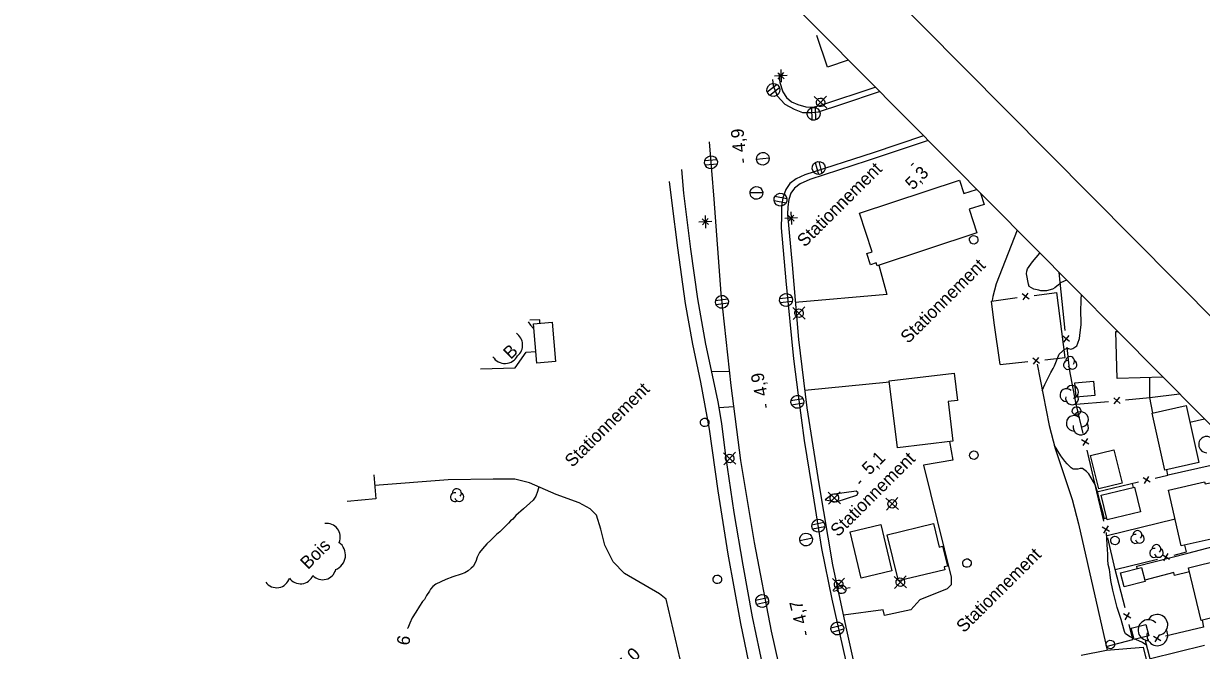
# Model space of a CAD drawing. Extents: x 381879 to 384696, y 5564785 to 5567594.
# Drawn here: x 383466.9 to 383743.2, y 5566826.8 to 5566973.9 of the extents above; entities that cross this region are included whole.
import ezdxf

# ---------------------------------------------------------------- set-up
doc = ezdxf.new("R2010")
doc.units = 0
for name, color, linetype in [('Niveau 19', 7, 'Continuous'), ('Niveau 2', 7, 'Continuous'), ('Niveau 21', 7, 'Continuous'), ('Niveau 22', 7, 'Continuous'), ('Niveau 3', 7, 'Continuous'), ('Niveau 31', 7, 'Continuous'), ('Niveau 36', 7, 'Continuous'), ('Niveau 37', 7, 'Continuous'), ('Niveau 44', 7, 'Continuous'), ('Niveau 52', 7, 'Continuous'), ('Niveau 60', 7, 'Continuous')]:
    doc.layers.add(name, color=color, linetype=linetype)

msp = doc.modelspace()

# ---------------------------------------------------------------- linework, layer by layer
at = {"layer": 'Niveau 19'}
for points in [[(383628.27, 5566892.24), (383632.51, 5566892.37)], [(383731.04, 5566886.19), (383731.06, 5566890.82)], [(383731.76, 5566882.51), (383731.04, 5566886.19), (383738.02, 5566887.03)], [(383633.53, 5566884.02), (383629.98, 5566883.76)], [(383743.88, 5566881.12), (383740.46, 5566880.28)], [(383735.4, 5566868.06), (383745.46, 5566870.32), (383750.86, 5566871.42)], [(383727.22, 5566865.09), (383727.01, 5566865.98)], [(383720.14, 5566857.72), (383720.96, 5566857.92)], [(383736.97, 5566857.62), (383721.08, 5566853.75)], [(383728.12, 5566846.05), (383728, 5566846.61), (383740.01, 5566849.62), (383750.71, 5566852.49), (383755.18, 5566853.7)], [(383740.33, 5566845.31), (383736.85, 5566844.41), (383736.66, 5566845.12), (383729.89, 5566843.36)], [(383743.88, 5566827.96), (383731.25, 5566824.83)]]:
    msp.add_lwpolyline(points, dxfattribs=at)
at = {"layer": 'Niveau 2'}
for points in [[(383711.54, 5566913.72), (383710.14, 5566913.05), (383709.67, 5566912.63), (383708.79, 5566911.9), (383708.21, 5566911.6), (383706.83, 5566911.17), (383705.5, 5566911.18), (383705, 5566911.36), (383703.85, 5566911.57), (383702.79, 5566912.2), (383702.63, 5566912.78), (383702.14, 5566915.17), (383702.2, 5566915.79), (383702.4, 5566916.36), (383702.73, 5566916.9), (383703.57, 5566918), (383705.3, 5566920.01)], [(383705.82, 5566887.83), (383706.45, 5566889.24), (383707.25, 5566890.76), (383707.85, 5566892.06), (383708.43, 5566892.98), (383708.72, 5566893.6), (383709.37, 5566895.2), (383709.79, 5566896.35), (383710.56, 5566897.03), (383711, 5566897.46), (383711.49, 5566897.63), (383712, 5566897.67), (383712.51, 5566897.53), (383713.03, 5566897.63), (383713.92, 5566898.3), (383714.16, 5566898.95), (383714.58, 5566900.01), (383714.68, 5566900.72), (383714.98, 5566903.31), (383714.95, 5566904.6), (383714.85, 5566905.67), (383714.86, 5566907.15), (383714.99, 5566908.22), (383714.99, 5566909.32), (383715.03, 5566910.2)], [(383585.28, 5566903.94), (383585.83, 5566903.16), (383586.62, 5566902.26)], [(383720.45, 5566857.79), (383720.22, 5566858.73), (383719.59, 5566861), (383718.92, 5566863.49), (383718.23, 5566865.77), (383717.87, 5566866.4), (383716.73, 5566868.27), (383716.23, 5566868.82), (383715.25, 5566869.55), (383714.73, 5566869.55), (383714.16, 5566869.38), (383713.12, 5566869.39), (383712.65, 5566869.66), (383711.64, 5566870.59), (383711.14, 5566871.2), (383710.17, 5566872.49), (383708.68, 5566874.89)], [(383587.78, 5566865.2), (383587.48, 5566864.09), (383587.08, 5566863.01), (383586.46, 5566862.08), (383585.68, 5566861.35), (383584.15, 5566860.05), (383582.41, 5566858.51), (383581.65, 5566857.64), (383581.11, 5566857.23), (383580.65, 5566856.71), (383578.64, 5566854.64), (383577.87, 5566854.02), (383576.55, 5566852.7), (383575.57, 5566851.81), (383574.56, 5566850.69), (383573.86, 5566849.82), (383573.32, 5566848.75), (383573.02, 5566847.71), (383572.36, 5566846.54), (383571.88, 5566846.17), (383571.2, 5566845.48), (383570.45, 5566845.02), (383569.55, 5566844.75), (383567.57, 5566844.1), (383565.95, 5566843.5), (383563.59, 5566842.41), (383562.95, 5566841.87), (383562.38, 5566841.24), (383562.11, 5566840.77), (383561.39, 5566839.73), (383560.92, 5566838.78), (383560.49, 5566838.31), (383559.76, 5566837.24), (383558.89, 5566835.85), (383558.08, 5566834.46), (383557.51, 5566833.27), (383557.03, 5566832.04), (383557.01, 5566831.98)], [(383724.35, 5566834.11), (383723.41, 5566836.93), (383723.01, 5566838.44), (383722.36, 5566841), (383721.93, 5566843.24), (383721.8, 5566844.57), (383721.57, 5566845.8), (383721.28, 5566846.98), (383721.18, 5566848.18), (383721.23, 5566849.41), (383721.13, 5566850.52), (383721.01, 5566852.91), (383720.91, 5566854.49)], [(383727.3, 5566829.63), (383726.42, 5566830.01), (383725.38, 5566830.73), (383725.12, 5566831.26), (383724.97, 5566831.82), (383724.35, 5566834.11)], [(383730.33, 5566827.97), (383729.31, 5566828.67), (383727.81, 5566829.41), (383727.64, 5566829.48)]]:
    msp.add_lwpolyline(points, dxfattribs=at)
at = {"layer": 'Niveau 21'}
for p, q in [((383643.8, 5566962.31), (383645.28, 5566960.95)), ((383643.88, 5566960.87), (383645.22, 5566962.37)), ((383644.49, 5566963.12), (383644.61, 5566960.12)), ((383646.05, 5566961.68), (383643.05, 5566961.56)), ((383626.75, 5566928.89), (383626.87, 5566925.89)), ((383646.18, 5566928.92), (383647.66, 5566927.56)), ((383646.26, 5566927.48), (383647.6, 5566928.98)), ((383646.87, 5566929.73), (383646.99, 5566926.73)), ((383628.31, 5566927.45), (383625.31, 5566927.33)), ((383626.06, 5566928.08), (383627.54, 5566926.72)), ((383626.14, 5566926.64), (383627.48, 5566928.14)), ((383648.43, 5566928.29), (383645.43, 5566928.17))]:
    msp.add_line(p, q, dxfattribs=at)
for points in [[(383642.56, 5566960.77), (383642.74, 5566959.36), (383643.67, 5566956.91), (383645.45, 5566954.99), (383647.62, 5566953.77), (383649.64, 5566953.02), (383651.76, 5566952.99), (383653.39, 5566953.22), (383658.82, 5566954.99), (383667.67, 5566957.94)], [(383737.49, 5566590.78), (383727.69, 5566609.79), (383718.09, 5566629.17), (383707.78, 5566649.57), (383698.39, 5566667.64), (383691.2, 5566682.96), (383683.79, 5566699.61), (383679.21, 5566710.93), (383672.16, 5566728.73), (383667.29, 5566742.33), (383662.12, 5566758.01), (383656.42, 5566775.1), (383651.76, 5566791.49), (383647.32, 5566809.08), (383642.31, 5566831.38), (383638.34, 5566852.16), (383635.18, 5566871.36), (383632.88, 5566888.99), (383630.5, 5566910.54), (383628.88, 5566932.68), (383627.83, 5566946.15)], [(383678, 5566947.53), (383666.2, 5566943.55), (383650.16, 5566938.44), (383648.13, 5566937.44), (383646.62, 5566936.34), (383645.69, 5566934.95), (383644.98, 5566933.04), (383644.71, 5566931.02), (383644.66, 5566928.83), (383644.62, 5566925.96), (383645.71, 5566913.54), (383647.49, 5566895.24), (383648.58, 5566886.69), (383650.03, 5566876.11), (383651.78, 5566865.06), (383654.07, 5566850.75), (383656.51, 5566838.83), (383659.71, 5566824.66)]]:
    msp.add_lwpolyline(points, dxfattribs=at)
at = {"layer": 'Niveau 22'}
for points in [[(383644.06, 5566962.25), (383644.29, 5566960.05), (383645.03, 5566957.84), (383645.83, 5566956.53), (383647.05, 5566955.55), (383648.51, 5566954.9), (383650.39, 5566954.37), (383652.01, 5566954.25), (383653.92, 5566954.72), (383666.64, 5566958.98)], [(383679.09, 5566946.43), (383664.74, 5566941.69), (383651.33, 5566937.32), (383649.04, 5566936.29), (383647.77, 5566935.31), (383646.9, 5566934.08), (383646.42, 5566932.62), (383646.2, 5566930.91), (383646.12, 5566929.13), (383647.18, 5566917.26), (383648.66, 5566899.78), (383650.66, 5566883.73), (383653.41, 5566865.9), (383656.68, 5566846.9), (383659.8, 5566832.31), (383662.88, 5566818.25)], [(383621.26, 5566939.64), (383621.73, 5566934.14), (383623.33, 5566920.99), (383624.95, 5566909.35), (383626.87, 5566898.7), (383628.68, 5566890.35), (383629.73, 5566885.18), (383630.63, 5566880.04), (383631.54, 5566872.5), (383633.51, 5566859.18), (383635.58, 5566846.83), (383637.83, 5566834.7), (383640.4, 5566822.49)], [(383637.98, 5566819.54), (383635.12, 5566833.17), (383632.21, 5566849.45), (383629.81, 5566864.25), (383627.81, 5566878.77), (383625.73, 5566889.76), (383623.89, 5566898.65), (383622.17, 5566908.21), (383620.37, 5566921.29), (383619.04, 5566931.72), (383618.45, 5566936.86)]]:
    msp.add_lwpolyline(points, dxfattribs=at)
at = {"layer": 'Niveau 3'}
for p, q in [((383635.78, 5566941.33), (383635.72, 5566942.13)), ((383675.06, 5566940.6), (383675.63, 5566941.17)), ((383641.06, 5566883.8), (383640.98, 5566884.6)), ((383662.8, 5566866.02), (383663.37, 5566866.59)), ((383650.43, 5566830.52), (383650.31, 5566831.32))]:
    msp.add_line(p, q, dxfattribs=at)
at = {"layer": 'Niveau 31'}
for points in [[(383660.35, 5566965.32), (383655.47, 5566963.68), (383652.98, 5566971.11)], [(383691.34, 5566934.07), (383692.2, 5566931.47), (383688.7, 5566930.32), (383690.53, 5566924.81), (383667.09, 5566917.06), (383666.85, 5566917.75), (383665.53, 5566917.31), (383664.66, 5566919.95), (383665.95, 5566920.37), (383662.98, 5566929.38), (383686.39, 5566937.12), (383687.42, 5566934), (383690.43, 5566935)], [(383734.16, 5566890.91), (383723.39, 5566890.6), (383723.07, 5566901.63), (383723.52, 5566901.64)], [(383549.08, 5566868.03), (383549.57, 5566862.38), (383542.79, 5566861.79)]]:
    msp.add_lwpolyline(points, dxfattribs=at)
for points in [[(383590.89, 5566903.87), (383591.72, 5566894.65), (383587.34, 5566894.26), (383586.51, 5566903.48)], [(383671.88, 5566874.38), (383669.96, 5566890.06), (383685.15, 5566891.9), (383685.93, 5566885.5), (383683.78, 5566885.24), (383684.9, 5566875.96)], [(383713.5, 5566889.59), (383717.87, 5566889.98), (383718.17, 5566886.61), (383713.8, 5566886.22)], [(383739.57, 5566884.27), (383742.56, 5566870.93), (383734.57, 5566869.13), (383731.58, 5566882.47)], [(383719.1, 5566864.75), (383717.17, 5566872.56), (383722.63, 5566873.91), (383724.56, 5566866.1)], [(383738.39, 5566851.34), (383735.43, 5566864.46), (383743.92, 5566866.37), (383744.02, 5566865.9), (383745.19, 5566866.17), (383746.54, 5566860.21), (383745.35, 5566859.95), (383746.87, 5566853.25)], [(383719.67, 5566863.26), (383727.45, 5566865.15), (383728.85, 5566859.37), (383721.07, 5566857.48)], [(383667.95, 5566856.35), (383670.53, 5566845.48), (383663.39, 5566843.78), (383660.81, 5566854.65)], [(383672.16, 5566843.13), (383669.5, 5566853.93), (383680.31, 5566856.58), (383681.65, 5566851.09), (383682.45, 5566851.29), (383683.59, 5566846.61), (383682.82, 5566846.42), (383682.98, 5566845.78)], [(383724.19, 5566845.05), (383729.13, 5566846.31), (383729.97, 5566843.04), (383725.03, 5566841.78)], [(383743.1, 5566833.85), (383740.1, 5566846.25), (383748.03, 5566848.17), (383748.61, 5566845.79), (383749.41, 5566845.99), (383750.25, 5566842.5), (383749.5, 5566842.32), (383751.09, 5566835.78)], [(383726.69, 5566832.04), (383730.15, 5566832.92), (383730.82, 5566830.29), (383727.36, 5566829.41)]]:
    msp.add_lwpolyline(points, close=True, dxfattribs=at)
at = {"layer": 'Niveau 36'}
for p, q in [((383643.66, 5566959.57), (383641.36, 5566957.79)), ((383641.94, 5566957.07), (383644.24, 5566958.85)), ((383652.38, 5566956.76), (383655.3, 5566954.04)), ((383652.48, 5566953.94), (383655.2, 5566956.86)), ((383651.73, 5566954.15), (383651.82, 5566951.26)), ((383652.73, 5566951.31), (383652.64, 5566954.2)), ((383629.53, 5566941.93), (383626.64, 5566941.67)), ((383626.75, 5566940.75), (383629.64, 5566941.01)), ((383641.8, 5566942.34), (383638.82, 5566942.02)), ((383652.61, 5566941.29), (383653.35, 5566938.49)), ((383654.23, 5566938.75), (383653.49, 5566941.55)), ((383640.3, 5566934.17), (383637.3, 5566934.15)), ((383642.94, 5566932.42), (383645.78, 5566931.83)), ((383645.94, 5566932.74), (383643.1, 5566933.33)), ((383647.12, 5566909.65), (383644.24, 5566909.34)), ((383632.07, 5566909.25), (383629.19, 5566908.88)), ((383629.33, 5566907.97), (383632.21, 5566908.34)), ((383644.36, 5566908.43), (383647.24, 5566908.74)), ((383647.33, 5566907.3), (383650.25, 5566904.58)), ((383647.43, 5566904.48), (383650.15, 5566907.4)), ((383649.74, 5566885.84), (383646.88, 5566885.37)), ((383647.04, 5566884.46), (383649.9, 5566884.93)), ((383631.07, 5566873.22), (383633.99, 5566870.5)), ((383631.17, 5566870.4), (383633.89, 5566873.32)), ((383655.61, 5566863.97), (383658.53, 5566861.25)), ((383655.71, 5566861.15), (383658.43, 5566864.07)), ((383669.17, 5566862.59), (383672.09, 5566859.87)), ((383669.27, 5566859.77), (383671.99, 5566862.69)), ((383654.61, 5566856.84), (383651.78, 5566856.24)), ((383651.99, 5566855.34), (383654.82, 5566855.94)), ((383651.93, 5566853.14), (383648.99, 5566852.56)), ((383656.61, 5566843.7), (383659.53, 5566840.98)), ((383656.71, 5566840.88), (383659.43, 5566843.8)), ((383671.09, 5566844.21), (383674.01, 5566841.49)), ((383671.19, 5566841.39), (383673.91, 5566844.31)), ((383656.85, 5566840.76), (383657.83, 5566840.97)), ((383660.77, 5566841.55), (383659.79, 5566841.36)), ((383641.45, 5566839.19), (383638.62, 5566838.58)), ((383638.83, 5566837.69), (383641.66, 5566838.3)), ((383659.04, 5566832.79), (383656.24, 5566832.04)), ((383656.5, 5566831.15), (383659.3, 5566831.9))]:
    msp.add_line(p, q, dxfattribs=at)
for centre, major_axis in [((383642.79, 5566958.32), (0.18, -1.51)), ((383652.23, 5566952.72), (0.18, -1.51)), ((383653.85, 5566955.4), (0.116, -0.993)), ((383628.15, 5566941.34), (-0.18, 1.51)), ((383640.3, 5566942.18), (-0.17, 1.49)), ((383653.42, 5566940.01), (0.18, -1.51)), ((383638.79, 5566934.16), (-0.17, 1.49)), ((383644.45, 5566932.57), (-0.18, 1.51)), ((383689.76, 5566923.16), (0.116, -0.993)), ((383630.71, 5566908.61), (-0.18, 1.51)), ((383645.75, 5566909.04), (-0.18, 1.51)), ((383648.8, 5566905.94), (0.116, -0.993)), ((383648.4, 5566885.15), (-0.18, 1.51)), ((383713.88, 5566883.01), (0.116, -0.993)), ((383626.66, 5566880.33), (0.116, -0.993)), ((383689.8, 5566872.63), (0.116, -0.993)), ((383632.54, 5566871.86), (0.116, -0.993)), ((383657.08, 5566862.61), (0.116, -0.993)), ((383670.64, 5566861.23), (0.116, -0.993)), ((383653.31, 5566856.09), (-0.18, 1.51)), ((383650.45, 5566852.85), (0.17, -1.49)), ((383722.89, 5566852.64), (0.116, -0.993)), ((383688.18, 5566847.33), (0.116, -0.993)), ((383629.64, 5566843.51), (0.116, -0.993)), ((383658.08, 5566842.34), (0.116, -0.993)), ((383672.56, 5566842.85), (0.116, -0.993)), ((383658.8, 5566841.16), (-0.116, 0.993)), ((383640.15, 5566838.44), (-0.18, 1.51)), ((383657.78, 5566831.97), (-0.18, 1.51)), ((383721.81, 5566828.23), (0.116, -0.993))]:
    msp.add_ellipse(centre, major_axis=major_axis, ratio=0.99999, dxfattribs=at)
at = {"layer": 'Niveau 37'}
for p, q in [((383711.19, 5566901.92), (383709.8, 5566915.47)), ((383702.76, 5566909.24), (383701.16, 5566910.47)), ((383701.35, 5566909.06), (383702.57, 5566910.65)), ((383703.94, 5566910.11), (383709.26, 5566910.83)), ((383712.2, 5566899.31), (383710.63, 5566900.56)), ((383712.04, 5566900.72), (383710.79, 5566899.15)), ((383712.23, 5566892.8), (383711.64, 5566897.95)), ((383695.96, 5566893.95), (383702.43, 5566894.58)), ((383705.2, 5566894.16), (383703.64, 5566895.42)), ((383703.79, 5566894.01), (383705.06, 5566895.57)), ((383713.8, 5566884.63), (383721.37, 5566885.27)), ((383724.13, 5566884.8), (383722.59, 5566886.09)), ((383722.72, 5566884.67), (383724.01, 5566886.21)), ((383725.36, 5566885.62), (383731.06, 5566886.19)), ((383716.43, 5566876.59), (383715.37, 5566874.89)), ((383716.75, 5566875.21), (383715.05, 5566876.27)), ((383718.65, 5566864.06), (383716.36, 5566873.79)), ((383718.65, 5566864.06), (383728.38, 5566866.35)), ((383731.18, 5566866.29), (383729.48, 5566867.34)), ((383729.8, 5566865.96), (383730.86, 5566867.67)), ((383720.27, 5566857.18), (383718.65, 5566864.06)), ((383721.59, 5566854.7), (383719.88, 5566855.76)), ((383721.26, 5566856.08), (383720.2, 5566854.37)), ((383722.95, 5566845.83), (383721.19, 5566853.28)), ((383735.7, 5566848.19), (383733.98, 5566849.23)), ((383734.32, 5566847.85), (383735.36, 5566849.57)), ((383722.95, 5566845.83), (383732.9, 5566848.23)), ((383725.25, 5566836.84), (383722.95, 5566845.83)), ((383726.59, 5566834.38), (383724.87, 5566835.42)), ((383726.25, 5566835.76), (383725.21, 5566834.04)), ((383731.94, 5566830.2), (383733.65, 5566829.16)), ((383733.32, 5566830.54), (383732.27, 5566828.82)), ((383730.85, 5566829.21), (383730.05, 5566829.08)), ((383735.04, 5566809.73), (383730.05, 5566829.08))]:
    msp.add_line(p, q, dxfattribs=at)
for points in [[(383695.96, 5566893.95), (383694.58, 5566903.72), (383693.95, 5566908.79), (383699.98, 5566909.6)], [(383706.41, 5566895), (383711.17, 5566895.54), (383709.26, 5566910.83)], [(383715.44, 5566877.69), (383713.8, 5566884.63), (383712.23, 5566892.8)], [(383732.28, 5566867.27), (383735.3, 5566867.97), (383735.06, 5566869.24)], [(383736.78, 5566849.19), (383739.68, 5566849.94), (383739.27, 5566851.54)], [(383720.8, 5566827.74), (383727.06, 5566829.42), (383726.21, 5566832.96)], [(383743.32, 5566833.9), (383743.68, 5566832.32), (383734.74, 5566830.15)]]:
    msp.add_lwpolyline(points, dxfattribs=at)
at = {"layer": 'Niveau 44'}
for centre, radius, start, end in [((383580.65, 5566898.49), 3.32, 310.2727, 55.4231), ((383579.84, 5566897.46), 3.32, 211.3078, 333.1582), ((383711.51, 5566886.73), 1.51, 44.1153, 269.8039), ((383712.81, 5566887.48), 1.51, 282.2692, 149.7262), ((383712.81, 5566885.98), 1.51, 166.9368, 29.6212), ((383713.3, 5566880.12), 1.81, 44.1153, 269.8039), ((383714.86, 5566881.03), 1.81, 282.2692, 149.7262), ((383714.86, 5566879.21), 1.81, 166.9368, 29.6212), ((383744.42, 5566875.12), 1.9, 44.1153, 269.8039), ((383538.06, 5566853.5), 3.14, 335.1751, 99.3208), ((383538.74, 5566849.2), 3.68, 292.1081, 53.973), ((383526.27, 5566844.71), 3.15, 215.8103, 343.4978), ((383531.88, 5566845.65), 3.17, 215.2844, 336.9614), ((383537.08, 5566846.58), 3.15, 223.5444, 345.4352), ((383732.83, 5566832.83), 2.44, 282.2692, 149.7262), ((383730.74, 5566831.61), 2.44, 44.1153, 269.8039), ((383732.83, 5566830.39), 2.44, 166.9368, 29.6212)]:
    msp.add_arc(centre, radius, start, end, dxfattribs=at)
for centre, start_param, end_param in [((383712.37, 5566894.73), 0.690957, 4.629966), ((383711.88, 5566893.81), 2.834597, 6.721173), ((383712.93, 5566893.85), 4.847526, 8.817401), ((383568.07, 5566862.8), 2.834597, 6.721173), ((383568.56, 5566863.72), 0.690957, 4.629966), ((383569.12, 5566862.84), 4.847526, 8.817401), ((383728.14, 5566853.92), 0.690957, 4.629966), ((383727.65, 5566853), 2.834597, 6.721173), ((383728.7, 5566853.04), 4.847526, 8.817401), ((383732.59, 5566850.62), 0.690957, 4.629966), ((383732.1, 5566849.7), 2.834597, 6.721173), ((383733.15, 5566849.74), 4.847526, 8.817401)]:
    msp.add_ellipse(centre, major_axis=(0.12, -1.04), ratio=0.99999, start_param=start_param, end_param=end_param, dxfattribs=at)
at = {"layer": 'Niveau 52'}
for points in [[(383699.95, 5566925.4), (383694.99, 5566912.84), (383694.26, 5566909.85), (383694.11, 5566908.92)], [(383667.51, 5566917.2), (383669.37, 5566910.3), (383647.92, 5566908.47)], [(383587.99, 5566903.61), (383588, 5566904.39), (383585.69, 5566904.35)], [(383574.11, 5566892.86), (383582.25, 5566893.14), (383584.84, 5566896.79), (383587.1, 5566896.95)], [(383704.61, 5566894.01), (383707.44, 5566879.59), (383708.86, 5566874.21), (383712.87, 5566862.26), (383714.34, 5566856.53), (383721.06, 5566826.91)], [(383650.14, 5566887.91), (383669.98, 5566889.87)], [(383684.11, 5566875.86), (383684.84, 5566871.48), (383678.01, 5566870.32), (383684.48, 5566844.03), (383684.44, 5566842.22), (383683.57, 5566841.31), (383677.09, 5566838.74), (383674.99, 5566836.33), (383668.86, 5566835.02), (383668.49, 5566836.39), (383659.19, 5566835.14)], [(383630.73, 5566803.43), (383627.26, 5566807.86), (383624.83, 5566811.91), (383623.21, 5566815.78), (383622.02, 5566820.06), (383617.61, 5566838.9), (383616.04, 5566840.15), (383607.88, 5566844.86), (383605.18, 5566847.66), (383603.28, 5566851.52), (383602.28, 5566855.27), (383601.31, 5566858.55), (383599.78, 5566860.02), (383597.22, 5566861.47), (383591.8, 5566863.45), (383585.61, 5566866.15), (383582.18, 5566867.05), (383577.08, 5566867.01), (383566.48, 5566866.86), (383549.3, 5566865.52)], [(383657.51, 5566861.69), (383662.36, 5566863.28), (383662.68, 5566863.79), (383662.19, 5566864.23), (383656.57, 5566863.41), (383654.95, 5566862.13), (383657.51, 5566861.69)], [(383714.98, 5566825.74), (383720.94, 5566826.9), (383729.52, 5566827.63), (383737.3, 5566795.84), (383722.61, 5566791.07), (383724.3, 5566785.69), (383710.54, 5566780.49), (383721.7, 5566751.41), (383723.03, 5566751.87), (383725.45, 5566745.15), (383696.36, 5566733.87), (383689.75, 5566731.2)]]:
    msp.add_lwpolyline(points, dxfattribs=at)
at = {"layer": 'Niveau 60'}
for points in [[(383794.43, 5567565.69), (383439.46, 5567213.56), (384312.69, 5566333.28), (384667.66, 5566685.41)], [(383653.8, 5566971.92), (383426.67, 5567200.87), (383197.47, 5566973.49), (381907.4, 5565693.71), (382780.65, 5564813.45), (384299.92, 5566320.61)]]:
    msp.add_lwpolyline(points, close=True, dxfattribs=at)

# ---------------------------------------------------------------- texts
at = {"layer": 'Niveau 2'}
msp.add_text('6', height=3, rotation=80.2368, dxfattribs=at).set_placement((383557.33, 5566827.87))
at = {"layer": 'Niveau 3'}
for s, rotation, p in [('4,9', 95.2738, (383636.26, 5566943.82)), ('5,3', 44.7717, (383675.46, 5566934.68)), ('4,9', 101.4456, (383641.45, 5566886.75)), ('5,1', 44.7717, (383665.34, 5566867.81)), ('4,7', 103.6075, (383650.7, 5566833.39)), ('5,0', 44.7717, (383607.88, 5566821.75))]:
    msp.add_text(s, height=3, rotation=rotation, dxfattribs=at).set_placement(p)
at = {"layer": 'Niveau 44'}
for s, p in [('B', (383581.2, 5566894.95)), ('Bois', (383533.63, 5566845.7))]:
    msp.add_text(s, height=3, rotation=44.7707, dxfattribs=at).set_placement(p)
at = {"layer": 'Niveau 52'}
for p in [(383650.12, 5566921.29), (383674.38, 5566898.66), (383595.64, 5566869.63), (383657.93, 5566853.32), (383687.46, 5566830.82)]:
    msp.add_text('Stationnement', height=3, rotation=44.7717, dxfattribs=at).set_placement(p)

doc.saveas('drawing.dxf')
